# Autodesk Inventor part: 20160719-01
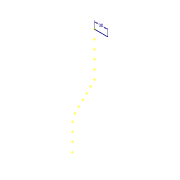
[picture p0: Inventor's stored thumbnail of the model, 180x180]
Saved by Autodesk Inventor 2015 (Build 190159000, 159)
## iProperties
Created: 2016-07
Part Number: 20160719-01
Material: Všeobecné
Document SubType Name: Modeling
Designer: navara
Density: 1 g/cm^3
Appearance: Výchozí
Author: navara
Mass: 0 g
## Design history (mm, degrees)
sketch "Náčrt1"
  geometry: L1 (0, 0)-(0, -100); L2 (0, -100)-(50, -200); L3 (50, -200)-(50, -300)
  constraints: 6 end point, 1 parallel, 1 vertical
  dimensions: "d0" = 100 distance of L1.start L1.end; "d1" = 100 distance of L2.end L3.end; "d2" = 100 vertical distance of L1.end L2.end; "d3" = 50 horizontal distance of L1.end L2.end
sketch "Náčrt2"
  geometry: L1 (0, 0)-(30, 0)
  constraints: 2 end point, 1 horizontal
  dimensions: "d4" = 30 distance of L1.start L1.end
node "Pracovní bod1"
pattern_linear "Obdélníkové pole1" dims "d7" = 20
node "Pracovní bod2"
node "Pracovní bod3"
node "Pracovní bod4"
node "Pracovní bod5"
node "Pracovní bod6"
node "Pracovní bod7"
node "Pracovní bod8"
node "Pracovní bod9"
node "Pracovní bod10"
node "Pracovní bod11"
node "Pracovní bod12"
node "Pracovní bod13"
node "Pracovní bod14"
node "Pracovní bod15"
